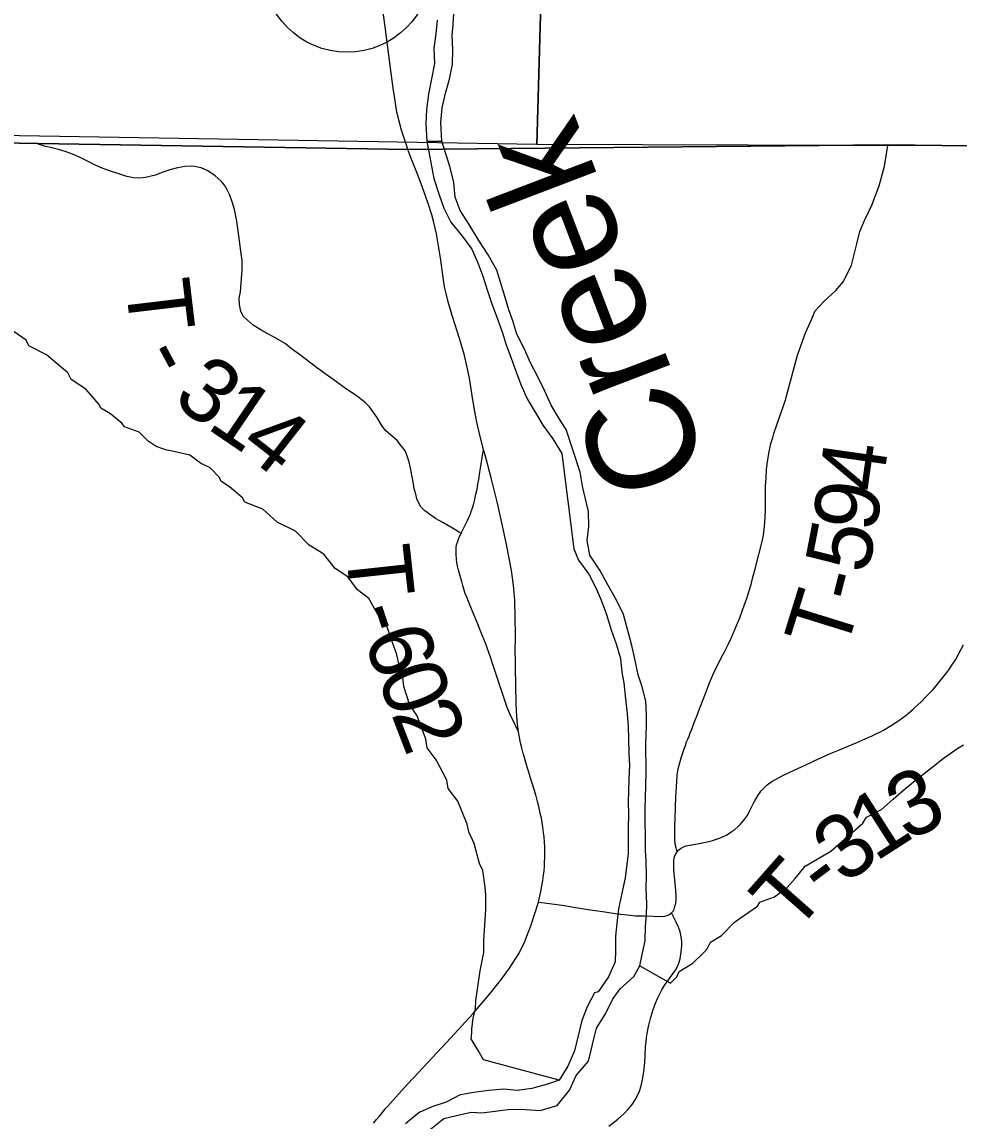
# Model space of a CAD drawing. Extents: x 0 to 34, y -8.9 to 22.
# Drawn here: x 26.715 to 27.543, y 16.454 to 17.424 of the extents above; entities that cross this region are included whole.
import ezdxf

# ---------------------------------------------------------------- set-up
doc = ezdxf.new("R2010")
doc.units = 0
for name, color, linetype in [('GM_X_Corporation', 7, 'Continuous'), ('GM_X_Major_River', 7, 'Continuous'), ('GM_X_Major_River_Text', 7, 'Continuous'), ('GM_X_Minor_River', 7, 'Continuous'), ('GM_X_State_Route', 7, 'Continuous'), ('GM_X_Township_Road', 7, 'Continuous'), ('GM_X_Township_Road_Text', 7, 'Continuous'), ('GM_X_Unincorporated', 7, 'Continuous')]:
    doc.layers.add(name, color=color, linetype=linetype)

msp = doc.modelspace()

# ---------------------------------------------------------------- linework, layer by layer
at = {"layer": 'GM_X_Corporation'}
for points in [[(26.14535, 18.31046), (27.19802, 18.31403), (27.16997, 17.31605), (26.13263, 17.33341)], [(28.20488, 18.30539), (28.20084, 17.74866), (28.19633, 17.31287), (27.16997, 17.31605), (27.19802, 18.31403)], [(23.71667, 15.99131), (23.71667, 14.6), (28.17389, 14.6), (28.1809, 15.29867), (28.19184, 16.15092), (28.18456, 16.33414), (28.1817, 16.6637), (28.19281, 16.80535), (28.18821, 17.31083), (27.91098, 17.31044), (27.47976, 17.3159), (27.05609, 17.31174), (26.72923, 17.31694), (26.39404, 17.3229), (26.13606, 17.32776), (26.13505, 17.30548), (26.11864, 15.93664), (25.79223, 15.93902), (25.67852, 15.94183), (24.82679, 15.96404), (24.27706, 15.98069), (24.06511, 15.98282)]]:
    msp.add_lwpolyline(points, close=True, dxfattribs=at)
for points in [[(26.13906, 17.88469), (26.13606, 17.32776), (26.39404, 17.3229), (26.72923, 17.31694), (27.05609, 17.31174), (27.47976, 17.3159), (27.91098, 17.31044), (28.18821, 17.31083), (28.201, 18.0921)], [(29.55275, 16.78351), (28.31818, 16.80017), (28.19281, 16.80535), (28.18821, 17.31083), (27.91098, 17.31044), (27.47976, 17.3159), (27.05609, 17.31174), (26.72923, 17.31694), (26.39404, 17.3229), (26.13606, 17.32776), (26.13906, 17.88469)], [(26.13906, 17.88469), (26.13606, 17.32776), (26.39404, 17.3229), (26.72923, 17.31694), (27.05609, 17.31174), (27.47976, 17.3159), (27.91098, 17.31044), (28.18821, 17.31083), (28.19281, 16.80535), (28.31818, 16.80017), (29.55275, 16.78351)]]:
    msp.add_lwpolyline(points, dxfattribs=at)
at = {"layer": 'GM_X_Major_River'}
msp.add_line((27.07257, 17.31907), (27.08589, 17.31897), dxfattribs=at)
for points in [[(27.08589, 17.31897), (27.08509, 17.33568), (27.08635, 17.3486), (27.08914, 17.36155), (27.09269, 17.37375), (27.09546, 17.38708), (27.09559, 17.3996), (27.09496, 17.41249), (27.09592, 17.42199), (27.09648, 17.43186)], [(27.08181, 17.42588), (27.08053, 17.41372), (27.07888, 17.40117), (27.07953, 17.38753), (27.07675, 17.3742), (27.07399, 17.3605), (27.07235, 17.34719), (27.07185, 17.33428), (27.07257, 17.31907)], [(27.07257, 17.31907), (27.07892, 17.28608), (27.08327, 17.27249), (27.08761, 17.26003), (27.09385, 17.2476), (27.10426, 17.23484), (27.11237, 17.22358), (27.11785, 17.21152), (27.12217, 17.19982), (27.12614, 17.18698), (27.1297, 17.17641), (27.13442, 17.16357), (27.13953, 17.14999), (27.14232, 17.14017), (27.14705, 17.12734), (27.15098, 17.11677), (27.1557, 17.10432), (27.16118, 17.0915), (27.16932, 17.07834), (27.17515, 17.06818), (27.18403, 17.05616), (27.19179, 17.04337), (27.20261, 16.95906)], [(27.19565, 17.06441), (27.18986, 17.07369), (27.18249, 17.0861), (27.17663, 17.09892), (27.17077, 17.11097), (27.16416, 17.1234), (27.15907, 17.13546), (27.15206, 17.14865), (27.14849, 17.16035), (27.14495, 17.17016), (27.14177, 17.18112), (27.13461, 17.2053), (27.12684, 17.21884), (27.11871, 17.23125), (27.11018, 17.24554), (27.10205, 17.25795), (27.09772, 17.26965), (27.09641, 17.28252), (27.09319, 17.29575), (27.08589, 17.31897)], [(27.20457, 16.494), (27.21556, 16.50665), (27.21775, 16.51654), (27.22031, 16.52643), (27.2225, 16.53595), (27.23035, 16.54855), (27.23668, 16.56114), (27.24342, 16.5707), (27.25546, 16.58144), (27.26069, 16.59098), (27.26287, 16.60088), (27.26541, 16.61305), (27.26568, 16.62558), (27.26672, 16.63584), (27.26701, 16.64534), (27.2665, 16.65976), (27.26678, 16.67001), (27.26628, 16.68329), (27.26581, 16.69316), (27.26546, 16.72998), (27.26575, 16.73948), (27.26603, 16.75011), (27.26631, 16.7615), (27.26607, 16.78693), (27.26668, 16.80251), (27.26659, 16.81238), (27.2661, 16.82452), (27.26294, 16.8374), (27.25943, 16.84799), (27.25626, 16.86201), (27.25388, 16.87376), (27.25034, 16.88701), (27.24641, 16.90102), (27.24022, 16.91387), (27.23251, 16.92746), (27.22556, 16.9403), (27.21671, 16.9535), (27.21431, 16.96639), (27.21571, 16.97893), (27.21559, 16.99222), (27.21244, 17.00434), (27.21007, 17.01456), (27.20806, 17.02669), (27.19565, 17.06441)], [(27.20261, 16.95906), (27.2065, 16.94923), (27.21572, 16.93679), (27.22229, 16.92395), (27.22656, 16.91374), (27.23123, 16.90125), (27.23553, 16.88763), (27.23982, 16.87514), (27.24374, 16.86227), (27.24499, 16.85013), (27.2466, 16.84066), (27.24824, 16.82663), (27.24951, 16.81335), (27.25037, 16.80197), (27.25085, 16.79172), (27.25097, 16.77844), (27.25182, 16.7682), (27.25118, 16.75566), (27.2509, 16.74541), (27.25061, 16.73553), (27.25071, 16.72528), (27.25046, 16.71161), (27.25066, 16.68998), (27.24782, 16.66869), (27.24455, 16.65347), (27.242, 16.6413), (27.24061, 16.62838), (27.23919, 16.61697), (27.23932, 16.60407), (27.23902, 16.59457), (27.23308, 16.58123), (27.2241, 16.56785)], [(27.2241, 16.56785), (27.22069, 16.56706), (27.21435, 16.55485), (27.20953, 16.54266), (27.20314, 16.51598)], [(27.20314, 16.51598), (27.19726, 16.50225), (27.18946, 16.49001), (27.17928, 16.48645), (27.1653, 16.48247), (27.15244, 16.48078), (27.14067, 16.48214), (27.12741, 16.48082), (27.11417, 16.47912), (27.10206, 16.47706), (27.08964, 16.47045), (27.07718, 16.46649), (27.06588, 16.4614), (27.05389, 16.45138)], [(27.07594, 16.44675), (27.08756, 16.45601), (27.0989, 16.45882), (27.11175, 16.46165), (27.12124, 16.46102), (27.14697, 16.4644), (27.16025, 16.4642), (27.17277, 16.46323), (27.18788, 16.46761), (27.19869, 16.48103), (27.20457, 16.494)]]:
    msp.add_lwpolyline(points, dxfattribs=at)
at = {"layer": 'GM_X_Minor_River'}
for points in [[(27.18946, 16.49001), (27.12274, 16.50789), (27.11815, 16.51625), (27.11169, 16.52645), (27.11235, 16.53216), (27.1123, 16.5352), (27.11366, 16.54434), (27.11578, 16.55311), (27.11604, 16.56033), (27.11976, 16.5866), (27.1229, 16.60261), (27.12309, 16.61325), (27.1249, 16.64063), (27.12467, 16.65355), (27.12417, 16.66038), (27.12202, 16.67516), (27.11926, 16.6812), (27.11844, 16.6846), (27.1144, 16.69897), (27.10966, 16.70916), (27.10841, 16.71598), (27.10008, 16.73636), (27.09153, 16.74762), (27.09027, 16.75482), (27.08085, 16.77291), (27.07307, 16.78342), (27.0718, 16.791), (27.06423, 16.81178), (27.05722, 16.82193), (27.0524, 16.83743), (27.0515, 16.84539), (27.0495, 16.85144), (27.04582, 16.86658), (27.04343, 16.873), (27.03664, 16.89264), (27.02888, 16.9024), (27.02144, 16.9152), (27.01143, 16.92302), (27.00289, 16.93428), (26.99175, 16.9417), (26.98166, 16.95446), (26.96862, 16.96224), (26.95664, 16.97458), (26.94055, 16.98269), (26.92782, 16.99427), (26.91177, 17.00047), (26.90981, 17.00424), (26.89825, 17.01393), (26.89058, 17.01875), (26.88938, 17.02215), (26.88126, 17.03076), (26.87284, 17.03481), (26.86322, 17.04187), (26.84645, 17.04579), (26.84303, 17.04612), (26.84035, 17.04721), (26.83348, 17.04938), (26.82657, 17.05421), (26.81846, 17.06206), (26.80547, 17.0668), (26.80352, 17.06981), (26.79312, 17.07838), (26.78469, 17.08319), (26.78311, 17.08658), (26.77149, 17.10007), (26.75843, 17.10861), (26.75567, 17.11464), (26.7368, 17.1303), (26.72109, 17.13841), (26.71873, 17.14331), (26.70336, 17.15409)], [(27.26069, 16.59098), (27.2879, 16.57548), (27.29348, 16.58127), (27.29567, 16.58585), (27.30766, 16.59327), (27.31697, 16.60254), (27.32032, 16.60601), (27.32325, 16.61174), (27.333, 16.61761), (27.34453, 16.62956), (27.34939, 16.63306), (27.36474, 16.64357), (27.36695, 16.64702), (27.37974, 16.65181), (27.39096, 16.65997), (27.39802, 16.66805), (27.40692, 16.67883), (27.42942, 16.69212), (27.45777, 16.71689), (27.46109, 16.72225), (27.47423, 16.72893), (27.48467, 16.73822), (27.494, 16.74635), (27.50259, 16.75332), (27.51193, 16.76069), (27.52015, 16.76729), (27.52875, 16.77388), (27.53585, 16.77894), (27.54184, 16.78322), (27.54671, 16.78596)]]:
    msp.add_lwpolyline(points, dxfattribs=at)
at = {"layer": 'GM_X_State_Route'}
for points in [[(27.04369, 17.36071), (27.04321, 17.36373), (27.04032, 17.38585), (27.03592, 17.42003), (27.02826, 17.47596)], [(27.05629, 17.3112), (27.05038, 17.32866), (27.04623, 17.34462), (27.04369, 17.36071)], [(27.02548, 16.45187), (27.02826, 16.4553), (27.03073, 16.4583), (27.0334, 16.46154), (27.03599, 16.46463), (27.03813, 16.46709), (27.04051, 16.46976), (27.04526, 16.47506), (27.05036, 16.48051), (27.05532, 16.48607), (27.06132, 16.49238), (27.06511, 16.49656), (27.06873, 16.50051), (27.0816, 16.51422), (27.09383, 16.52744), (27.10647, 16.5411), (27.11353, 16.54884), (27.12011, 16.55641), (27.12832, 16.56627), (27.13658, 16.57645), (27.14028, 16.58139), (27.14568, 16.58894), (27.1511, 16.59716), (27.15381, 16.60162), (27.15612, 16.60591), (27.1585, 16.61099), (27.16106, 16.61707), (27.16451, 16.62634), (27.16849, 16.63809), (27.17117, 16.64727), (27.17335, 16.65662), (27.17516, 16.66633), (27.17581, 16.67091), (27.17619, 16.67491), (27.17655, 16.67889), (27.17671, 16.6823), (27.17688, 16.68686), (27.17688, 16.69155), (27.1768, 16.69582), (27.17656, 16.70017), (27.17622, 16.7047), (27.17579, 16.70877), (27.17524, 16.71341), (27.17458, 16.71744), (27.17392, 16.72122), (27.17291, 16.72577), (27.17161, 16.73149), (27.17037, 16.73597), (27.16882, 16.74194), (27.16718, 16.74744), (27.16598, 16.75144), (27.16436, 16.75676), (27.16268, 16.76204), (27.16142, 16.7662), (27.15945, 16.77268), (27.15776, 16.77873), (27.15649, 16.78328), (27.15551, 16.78779), (27.15454, 16.79268), (27.15369, 16.79747), (27.15288, 16.80438), (27.15231, 16.81119), (27.15167, 16.82234), (27.15152, 16.82668), (27.15126, 16.83473), (27.15118, 16.84154), (27.15098, 16.85084), (27.15101, 16.85705), (27.15084, 16.86262), (27.15083, 16.86696), (27.15098, 16.88311), (27.15082, 16.89862), (27.15027, 16.91349), (27.14951, 16.92399), (27.14872, 16.93136), (27.14747, 16.93993), (27.14545, 16.95089), (27.143, 16.96306), (27.14094, 16.97278), (27.13496, 16.99943), (27.12984, 17.02054), (27.12473, 17.03973), (27.12285, 17.04676), (27.11942, 17.05956), (27.11676, 17.07109), (27.11498, 17.08027), (27.11299, 17.09255), (27.11027, 17.10971), (27.10813, 17.12065), (27.10567, 17.13088), (27.10194, 17.14398), (27.095, 17.16523), (27.09142, 17.17717), (27.0896, 17.18444), (27.08832, 17.19056), (27.087, 17.19856), (27.08506, 17.21397), (27.08338, 17.225), (27.08112, 17.23715), (27.07884, 17.24738), (27.07705, 17.25392), (27.07387, 17.26392), (27.06853, 17.27908), (27.06435, 17.29006), (27.05804, 17.30625), (27.05629, 17.3112)]]:
    msp.add_lwpolyline(points, dxfattribs=at)
at = {"layer": 'GM_X_Township_Road'}
for points in [[(27.10298, 16.97276), (27.10097, 16.97392), (27.09872, 16.97522), (27.09192, 16.97949), (27.08685, 16.98239), (27.08027, 16.98584), (27.0761, 16.98873), (27.07093, 16.99277), (27.06717, 16.99658), (27.06376, 17.00325), (27.06289, 17.00749), (27.06152, 17.01203), (27.06088, 17.01664), (27.05866, 17.02883), (27.0574, 17.03437), (27.05558, 17.04025), (27.05342, 17.04564), (27.0503, 17.04964), (27.04651, 17.05475), (27.03643, 17.06339), (27.03323, 17.06745), (27.02905, 17.07454), (27.02588, 17.07909), (27.02191, 17.08446), (27.01845, 17.08797), (27.0142, 17.09153), (27.0084, 17.09561), (27.00079, 17.10078), (26.99289, 17.1067), (26.98387, 17.11292), (26.9753, 17.11914), (26.96005, 17.13086), (26.9531, 17.13565), (26.94764, 17.1403), (26.93651, 17.14649), (26.92789, 17.15141), (26.91927, 17.15663), (26.91396, 17.16127), (26.91064, 17.16433), (26.90837, 17.16866), (26.90729, 17.17475), (26.907, 17.18051), (26.90793, 17.18615), (26.90958, 17.20534), (26.90956, 17.21372), (26.90846, 17.22209), (26.90708, 17.23119), (26.90493, 17.2484), (26.90288, 17.25862), (26.90084, 17.26547), (26.89855, 17.27131), (26.89624, 17.27597), (26.89397, 17.28021), (26.89095, 17.28372), (26.88575, 17.28847), (26.87928, 17.29278), (26.87321, 17.29556), (26.86591, 17.29714), (26.85882, 17.2967), (26.85253, 17.29558), (26.84573, 17.29381), (26.83948, 17.29177), (26.83307, 17.28913), (26.824, 17.28696), (26.81891, 17.28644), (26.8135, 17.28677), (26.80768, 17.28788), (26.8006, 17.29019), (26.79234, 17.29303), (26.78586, 17.29511), (26.77864, 17.29839), (26.7742, 17.30079), (26.76706, 17.30436), (26.7604, 17.30738), (26.75303, 17.30998), (26.74722, 17.31169), (26.74029, 17.31348), (26.73499, 17.31466), (26.72943, 17.31641)], [(27.29378, 16.69161), (27.29292, 16.69522), (27.29216, 16.69839), (27.29171, 16.70273), (27.29164, 16.70769), (27.29169, 16.7114), (27.29183, 16.71512), (27.292, 16.72009), (27.29241, 16.73127), (27.29274, 16.73998), (27.29341, 16.75365), (27.29385, 16.75922), (27.29472, 16.76473), (27.29553, 16.76821), (27.29748, 16.77469), (27.29865, 16.77821), (27.29996, 16.78244), (27.30106, 16.7855), (27.30215, 16.78856), (27.30324, 16.79119), (27.30434, 16.79382), (27.30534, 16.79655), (27.30698, 16.80054), (27.3089, 16.80573), (27.31107, 16.8115), (27.31267, 16.81549), (27.31813, 16.82993), (27.32229, 16.84066), (27.32404, 16.84503), (27.32689, 16.85117), (27.33017, 16.85773), (27.33257, 16.86277), (27.33564, 16.86824), (27.33914, 16.87524), (27.34177, 16.88071), (27.34483, 16.88793), (27.34902, 16.89834), (27.35116, 16.90416), (27.35339, 16.90995), (27.35534, 16.9153), (27.35687, 16.92033), (27.35914, 16.92766), (27.36037, 16.93303), (27.36279, 16.94148), (27.36944, 16.96799), (27.37039, 16.97344), (27.37078, 16.97651), (27.37131, 16.98205), (27.37159, 16.98761), (27.37174, 16.99253), (27.37175, 16.99378), (27.37179, 16.9962), (27.37181, 16.99743), (27.37184, 17.00042), (27.37186, 17.00712), (27.37197, 17.0145), (27.37228, 17.02192), (27.37286, 17.02936), (27.37382, 17.03801), (27.375, 17.04473), (27.37666, 17.05199), (27.37819, 17.05737), (27.3793, 17.06092), (27.38187, 17.06847), (27.38423, 17.0753), (27.38773, 17.08551), (27.38937, 17.09073), (27.39148, 17.09847), (27.40023, 17.13026), (27.40711, 17.14995), (27.4118, 17.16027), (27.41574, 17.16922), (27.42337, 17.17747), (27.434, 17.18717), (27.44088, 17.19529), (27.44776, 17.20968), (27.45245, 17.22844), (27.45527, 17.23938), (27.45933, 17.24907), (27.46589, 17.26252), (27.47215, 17.27972), (27.47684, 17.29692), (27.47997, 17.31537)], [(27.10298, 16.97276), (27.10341, 16.97353), (27.10871, 16.98405), (27.1099, 16.98668), (27.11092, 16.98916), (27.11196, 16.99198), (27.11274, 16.99442), (27.11376, 16.9981), (27.11468, 17.00158), (27.11598, 17.00727), (27.117, 17.01182), (27.11783, 17.0161), (27.11856, 17.02033), (27.11955, 17.02683), (27.12042, 17.03213), (27.12165, 17.03986), (27.12285, 17.04676)], [(27.15369, 16.79747), (27.14803, 16.80926), (27.14671, 16.81201), (27.14346, 16.82004), (27.13912, 16.83228), (27.13383, 16.84811), (27.13152, 16.85516), (27.12878, 16.86335), (27.12618, 16.87093), (27.12494, 16.87436), (27.11983, 16.88737), (27.11731, 16.89363), (27.1143, 16.90101), (27.11013, 16.91126), (27.108, 16.91637), (27.10665, 16.91982), (27.10537, 16.9235), (27.10443, 16.92687), (27.10348, 16.93022), (27.10266, 16.93317), (27.10183, 16.93616), (27.10064, 16.94031), (27.09975, 16.94401), (27.09921, 16.94689), (27.09876, 16.95026), (27.09851, 16.95384), (27.09843, 16.95601), (27.09845, 16.95847), (27.09861, 16.96027), (27.09896, 16.96267), (27.09964, 16.9651), (27.10092, 16.96857), (27.10252, 16.97191), (27.10298, 16.97276)], [(27.29378, 16.69161), (27.29529, 16.69332), (27.29725, 16.69483), (27.29943, 16.69598), (27.30178, 16.69676), (27.30659, 16.6978), (27.31014, 16.69844), (27.31319, 16.69883), (27.31754, 16.69975), (27.32166, 16.7006), (27.32522, 16.70167), (27.32755, 16.7025), (27.33045, 16.70345), (27.33331, 16.70464), (27.33444, 16.70513), (27.33724, 16.70643), (27.34036, 16.70835), (27.34246, 16.70969), (27.34447, 16.71114), (27.34781, 16.71392), (27.34959, 16.71564), (27.35162, 16.71797), (27.35387, 16.72093), (27.35556, 16.72347), (27.35676, 16.72553), (27.35811, 16.72794), (27.36167, 16.73509), (27.36277, 16.73731), (27.3653, 16.74158), (27.36669, 16.74362), (27.3678, 16.7451), (27.37028, 16.74786), (27.37294, 16.75046), (27.37485, 16.75203), (27.37795, 16.75407), (27.38009, 16.75529), (27.38282, 16.75676), (27.38785, 16.75919), (27.39345, 16.76182), (27.40689, 16.76819), (27.4142, 16.77161), (27.41872, 16.77368), (27.42833, 16.77801), (27.43576, 16.78117), (27.45181, 16.78786), (27.46264, 16.79252), (27.46603, 16.79406), (27.46939, 16.79565), (27.4727, 16.79731), (27.476, 16.79902), (27.48296, 16.80305), (27.48969, 16.80751), (27.49613, 16.81239), (27.50231, 16.81756), (27.50416, 16.81921), (27.50914, 16.82378), (27.51384, 16.82862), (27.51644, 16.83126), (27.51935, 16.83446), (27.52139, 16.83679), (27.52615, 16.84252), (27.53188, 16.84987), (27.53372, 16.85237), (27.5359, 16.85538), (27.53963, 16.86108), (27.5427, 16.86671), (27.5466, 16.87425)], [(27.2888, 16.63763), (27.29015, 16.63924), (27.29102, 16.64088), (27.29187, 16.64321), (27.29254, 16.64623), (27.29277, 16.64959), (27.29278, 16.65242), (27.29253, 16.65737), (27.29185, 16.66664), (27.29099, 16.67592), (27.29078, 16.68152), (27.291, 16.68461), (27.29152, 16.68704), (27.29239, 16.68934), (27.29378, 16.69161)], [(27.17117, 16.64727), (27.1766, 16.64656), (27.18763, 16.64513), (27.19435, 16.64408), (27.2023, 16.64281), (27.21516, 16.6408), (27.22988, 16.63853), (27.24094, 16.63689), (27.25264, 16.63551), (27.25696, 16.6352), (27.25943, 16.63511), (27.26502, 16.63499), (27.27992, 16.63461), (27.28302, 16.63487), (27.28483, 16.63526), (27.28655, 16.63597), (27.2888, 16.63763)], [(27.23353, 16.44934), (27.24131, 16.45553), (27.24686, 16.4605), (27.25076, 16.46451), (27.25391, 16.46835), (27.25666, 16.47249), (27.25872, 16.47631), (27.26042, 16.48031), (27.26194, 16.48505), (27.26322, 16.49048), (27.26439, 16.49719), (27.2653, 16.50521), (27.26565, 16.51202), (27.26592, 16.51947), (27.26627, 16.5238), (27.26663, 16.5275), (27.26716, 16.53118), (27.26833, 16.53728), (27.27016, 16.5445), (27.27238, 16.55162), (27.27475, 16.55802), (27.27672, 16.56259), (27.28038, 16.56979), (27.28296, 16.57402), (27.28543, 16.5776), (27.28764, 16.5806), (27.29223, 16.58723), (27.29441, 16.591), (27.29538, 16.59327), (27.2964, 16.59718), (27.2973, 16.60337), (27.29778, 16.60857), (27.29778, 16.61229), (27.29731, 16.61661), (27.29641, 16.62087), (27.29505, 16.625), (27.29303, 16.62954), (27.29188, 16.63174), (27.2888, 16.63763)]]:
    msp.add_lwpolyline(points, dxfattribs=at)
at = {"layer": 'GM_X_Unincorporated'}
msp.add_circle((27.00216, 17.47204), 0.0744, dxfattribs=at)

# ---------------------------------------------------------------- texts
at = {"layer": 'GM_X_Major_River_Text'}
msp.add_text('Creek', height=0.094687, rotation=110.90556, dxfattribs=at).set_placement((27.32323, 17.02792))
at = {"layer": 'GM_X_Township_Road_Text'}
for s, rotation, p in [('T', 276.7827, (26.8062, 17.19394)), ('-', 298.35968, (26.81822, 17.12963)), ('3', 323.08819, (26.84661, 17.08899)), ('1', 325.77077, (26.87696, 17.06628)), ('4', 322.031, (26.9051, 17.04718)), ('4', 81.89216, (27.47452, 17.00778)), ('9', 81.28383, (27.46912, 16.97253)), ('5', 79.07283, (27.46208, 16.93582)), ('T', 276.19206, (27.00074, 16.95936)), ('-', 75.79877, (27.45558, 16.90974)), ('T', 72.71167, (27.44205, 16.86595)), ('-', 288.6001, (27.00819, 16.90403)), ('6', 290.06612, (27.01616, 16.88042)), ('0', 290.47083, (27.02832, 16.84713)), ('2', 291.17856, (27.04083, 16.81363)), ('3', 26.0856, (27.49676, 16.70033)), ('1', 32.68551, (27.4688, 16.68228)), ('3', 36.86989, (27.4417, 16.66191)), ('T', 48.56007, (27.39718, 16.61809)), ('-', 36.96981, (27.42308, 16.64789))]:
    msp.add_text(s, height=0.05682, rotation=rotation, dxfattribs=at).set_placement(p)

doc.saveas('drawing.dxf')
